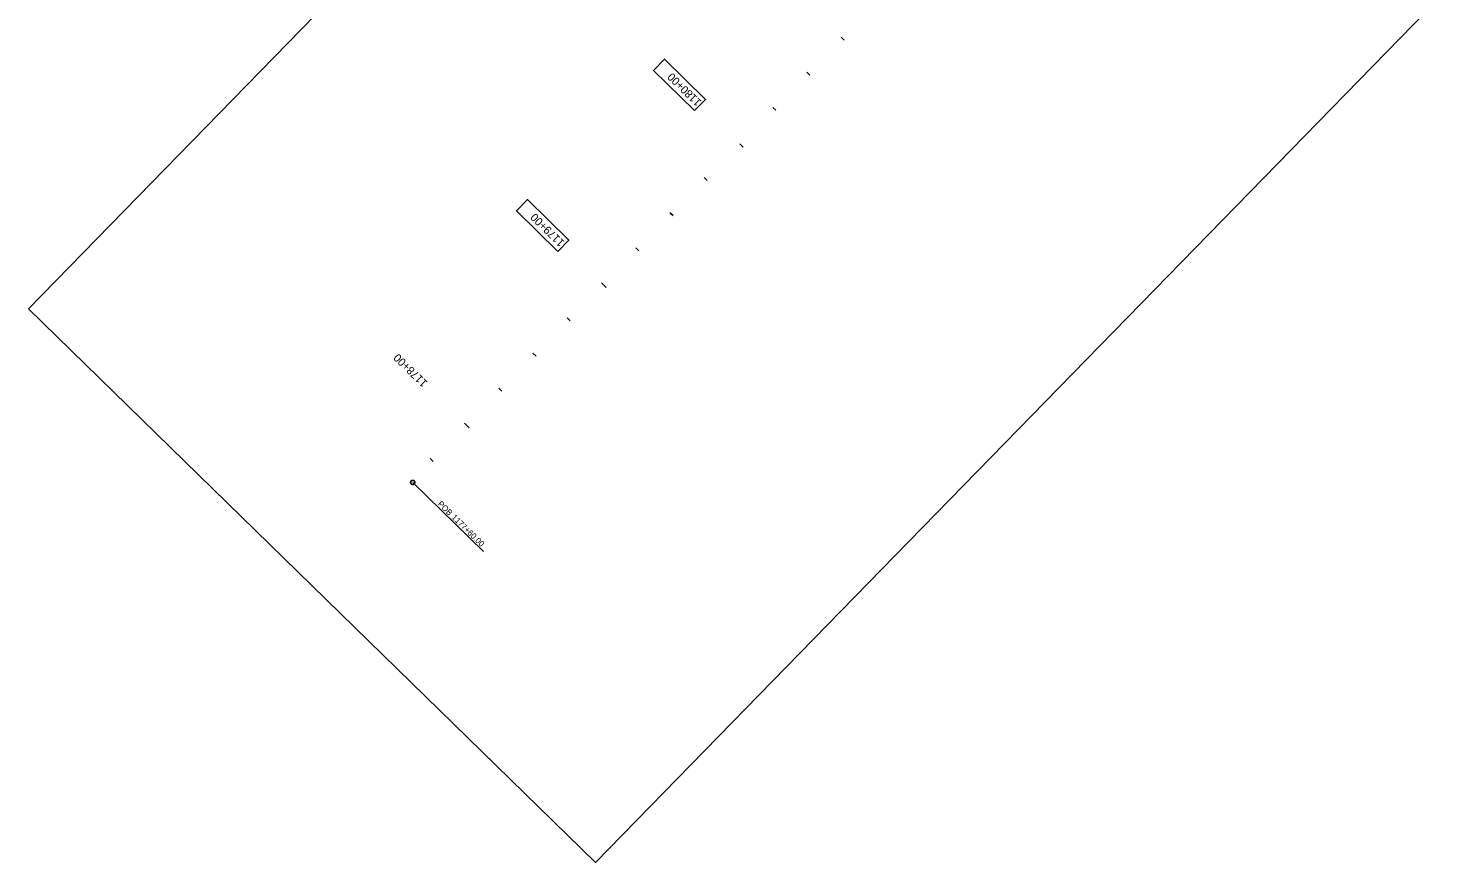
# Model space of a CAD drawing. Extents: x 19420655 to 19421801, y 7630893 to 7632053.
# Drawn here: x 19420655 to 19421382, y 7630893 to 7631318 of the extents above; entities that cross this region are included whole.
import ezdxf

# ---------------------------------------------------------------- set-up
doc = ezdxf.new("R2010")
doc.units = 0
for name, color, linetype in [('Level 1', 7, 'Continuous'), ('Level 3', 7, 'Continuous'), ('Level 4', 7, 'Continuous'), ('Level 5', 7, 'Continuous'), ('Level 6', 7, 'Continuous')]:
    doc.layers.add(name, color=color, linetype=linetype)

msp = doc.modelspace()

# ---------------------------------------------------------------- linework, layer by layer
at = {"layer": 'Level 1'}
for p, q in [((19421017.33, 7631259.2), (19421019.08, 7631257.49)), ((19420948.37, 7631186.77), (19420946.8, 7631188.3)), ((19420878.53, 7631115.2), (19420876.96, 7631116.73))]:
    msp.add_line(p, q, dxfattribs=at)
at = {"layer": 'Level 3'}
for p in [(19420850.59, 7631086.57), (19420886.66, 7631051.37)]:
    msp.add_line(p, (19420886.66, 7631051.37), dxfattribs=at)
msp.add_circle((19420850.59, 7631086.57), 1.07, dxfattribs=at)
at = {"layer": 'Level 4'}
for p, q in [((19421070.59, 7631312.02), (19421069.02, 7631313.55)), ((19421053.13, 7631294.13), (19421051.56, 7631295.65)), ((19421035.67, 7631276.24), (19421034.1, 7631277.76)), ((19421017.33, 7631259.2), (19421019.08, 7631257.49)), ((19421000.75, 7631240.45), (19420999.18, 7631241.98)), ((19420983.29, 7631222.56), (19420981.72, 7631224.08)), ((19420965.83, 7631204.66), (19420964.26, 7631206.19)), ((19420947.49, 7631187.63), (19420949.24, 7631185.92)), ((19420930.91, 7631168.88), (19420929.34, 7631170.4)), ((19420913.45, 7631150.99), (19420911.88, 7631152.51)), ((19420895.99, 7631133.09), (19420894.42, 7631134.62)), ((19420877.65, 7631116.06), (19420879.4, 7631114.35)), ((19420861.07, 7631097.31), (19420859.5, 7631098.83))]:
    msp.add_line(p, q, dxfattribs=at)
at = {"layer": 'Level 5'}
msp.add_lwpolyline([(19420654.69, 7631175.05), (19421092.58, 7631623.79), (19421381.73, 7631341.64), (19420943.83, 7630892.89)], close=True, dxfattribs=at)
at = {"layer": 'Level 6'}
for points in [[(19420994.32, 7631276.07), (19420999.9, 7631281.79), (19420978.87, 7631302.32), (19420973.28, 7631296.59)], [(19420924.63, 7631204.35), (19420930.22, 7631210.07), (19420909.02, 7631230.75), (19420903.44, 7631225.03)]]:
    msp.add_lwpolyline(points, close=True, dxfattribs=at)

# ---------------------------------------------------------------- texts
at = {"layer": 'Level 1'}
msp.add_text('1180+00', height=4.08, rotation=135.70104, dxfattribs=at).set_placement((19420998.16, 7631280.75))
at = {"layer": 'Level 3'}
for s, p in [('POB ', (19420863.07, 7631075.31)), ('1177+60.00', (19420870.13, 7631068.43))]:
    msp.add_text(s, height=3, rotation=315.70104, dxfattribs=at).set_placement(p)
at = {"layer": 'Level 4'}
for s, p in [('1180+00', (19420998.16, 7631280.75)), ('1179+00', (19420928.32, 7631209.18)), ('1178+00', (19420858.48, 7631137.61))]:
    msp.add_text(s, height=4.08, rotation=135.70104, dxfattribs=at).set_placement(p)

doc.saveas('drawing.dxf')
